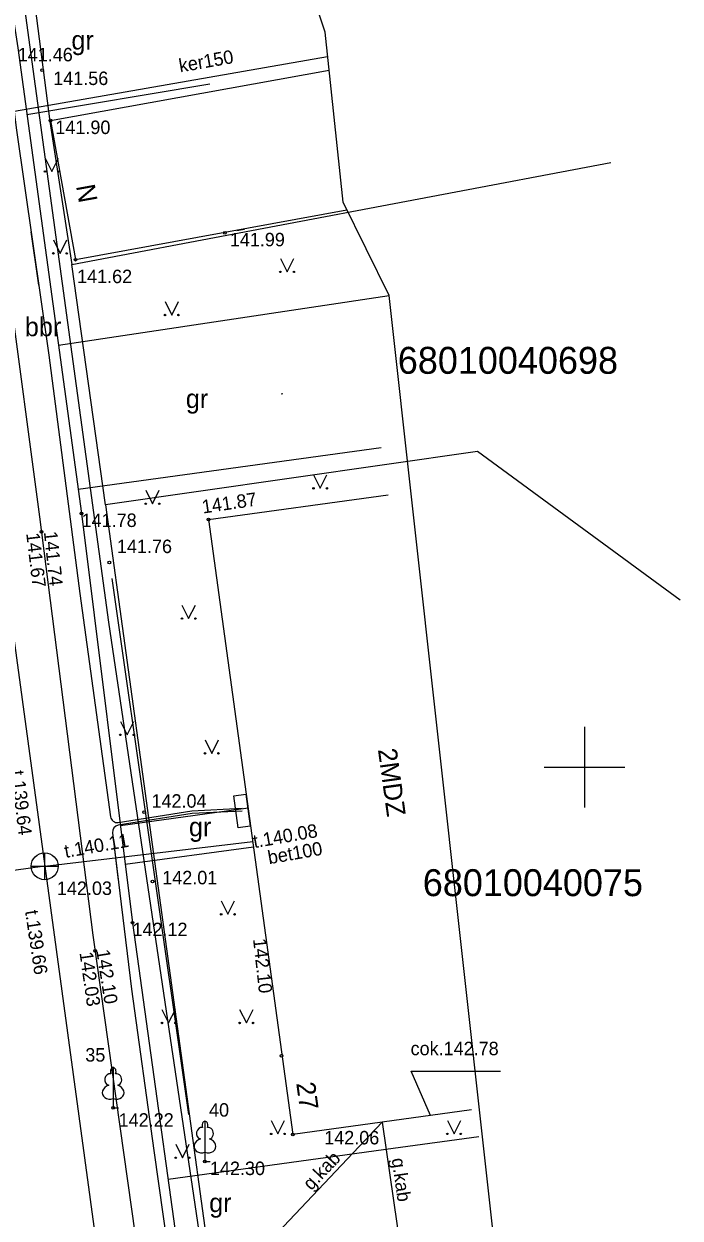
# Model space of a CAD drawing. Extents: x 728710 to 728960, y 272811 to 273475.
# Drawn here: x 728829.17 to 728853.55, y 273033.26 to 273077.6 of the extents above; entities that cross this region are included whole.
import ezdxf

# ---------------------------------------------------------------- set-up
doc = ezdxf.new("R2010")
doc.units = 0
for name, color, linetype in [('Level 10', 7, 'Continuous'), ('Level 15', 7, 'Continuous'), ('Level 20', 7, 'Continuous'), ('Level 23', 7, 'Continuous'), ('Level 29', 7, 'Continuous'), ('Level 3', 7, 'Continuous'), ('Level 36', 7, 'Continuous'), ('Level 4', 7, 'Continuous'), ('Level 48', 7, 'Continuous'), ('Level 5', 7, 'Continuous'), ('Level 50', 7, 'Continuous'), ('Level 56', 7, 'Continuous'), ('Level 57', 7, 'Continuous'), ('Level 58', 7, 'Continuous'), ('Level 59', 7, 'Continuous'), ('Level 60', 7, 'Continuous'), ('Level 62', 7, 'Continuous'), ('Level 9', 7, 'Continuous'), ('RAMI_UZMR_####_####_#', 7, 'Continuous'), ('RELJ_NOGA_####_####_#', 7, 'Continuous'), ('RELJ_NOGL_####_####_#', 7, 'Continuous'), ('ROBZ_ELEM_####_####_#', 7, 'Continuous'), ('ROBZ_KADS_####_TKST_#', 7, 'Continuous'), ('ROBZ_UZMR_####_####_#', 7, 'Continuous'), ('SAKT_VADV_PKAB_TKST_#', 7, 'Continuous'), ('TERT_ELEM_####_####_#', 7, 'Continuous'), ('TERT_KONT_####_####_#', 7, 'Continuous')]:
    doc.layers.add(name, color=color, linetype=linetype)

msp = doc.modelspace()

# ---------------------------------------------------------------- linework, layer by layer
at = {"layer": 'Level 10'}
for p, q in [((728850, 273051.5), (728850, 273050)), ((728848.5, 273050), (728850, 273050)), ((728850, 273050), (728850, 273048.5)), ((728850, 273050), (728851.5, 273050))]:
    msp.add_line(p, q, dxfattribs=at)
at = {"layer": 'Level 15'}
msp.add_lwpolyline([(728837.131, 273047.752), (728836.966, 273048.94), (728837.412, 273049.002), (728837.576, 273047.813)], close=True, dxfattribs=at)
at = {"layer": 'Level 20'}
msp.add_line((728838.728, 273063.858), (728838.788, 273063.88), dxfattribs=at)
at = {"layer": 'Level 23'}
for points in [[(728821.624, 273100.995), (728826.189, 273073.896), (728840.452, 273076.388)], [(728826.189, 273073.896), (728833.694, 273018.747), (728821.168, 273017.069)], [(728829.942, 273046.322), (728837.671, 273047.239)], [(728829.942, 273046.322), (728821.163, 273045.101)]]:
    msp.add_lwpolyline(points, dxfattribs=at)
at = {"layer": 'Level 29'}
for p, q in [((728829.942, 273045.822), (728829.942, 273046.822)), ((728829.442, 273046.322), (728830.442, 273046.322))]:
    msp.add_line(p, q, dxfattribs=at)
msp.add_circle((728829.942, 273046.322), 0.5, dxfattribs=at)
at = {"layer": 'Level 3'}
for p, q in [((728830.155, 273074.012), (728840.506, 273075.886)), ((728830.155, 273074.012), (728831.09, 273068.845)), ((728831.09, 273068.845), (728841.169, 273070.698)), ((728836.029, 273059.195), (728842.701, 273060.111)), ((728836.029, 273059.195), (728839.164, 273036.364)), ((728845.796, 273037.275), (728839.164, 273036.364))]:
    msp.add_line(p, q, dxfattribs=at)
at = {"layer": 'Level 36'}
for points in [[(728829.721, 273067.896), (728829.437, 273069.878)], [(728832.465, 273047.568), (728832.677, 273045.803)]]:
    msp.add_lwpolyline(points, dxfattribs=at)
at = {"layer": 'Level 4'}
for p, q in [((728832.754, 273047.833), (728837.5, 273048.485)), ((728832.933, 273046.393), (728837.697, 273047.047)), ((728842.887, 273035.853), (728846.065, 273036.289)), ((728834.526, 273034.705), (728842.887, 273035.853))]:
    msp.add_line(p, q, dxfattribs=at)
for points in [[(728845.654, 273100.85), (728832.719, 273098.413), (728826.071, 273097.316), (728825.017, 273097.001), (728824.765, 273096.832), (728824.532, 273096.455), (728824.532, 273096.455), (728826.161, 273084.877), (728827.437, 273076.575), (728829.749, 273059.3), (728831.728, 273043.761), (728834.021, 273027.538), (728834.782, 273021.709), (728836.279, 273011.943), (728839.357, 272993.501), (728839.499, 272992.383), (728841.21, 272978.381), (728843.301, 272966.86), (728843.797, 272965.94)], [(728845.919, 273099.374), (728832.98, 273096.936), (728826.409, 273095.852), (728826.143, 273095.772), (728827.647, 273085.083), (728828.941, 273076.709), (728831.314, 273059.418), (728833.202, 273044.226), (728835.526, 273027.512), (728836.266, 273021.924), (728837.76, 273012.18), (728840.331, 272994.327), (728840.331, 272994.327), (728840.331, 272994.327), (728842.687, 272979.229), (728844.615, 272968.066)], [(728829.28, 273074.24), (728836.077, 273075.379)], [(728830.456, 273065.669), (728842.745, 273067.512)], [(728831.189, 273060.327), (728842.448, 273061.866)]]:
    msp.add_lwpolyline(points, dxfattribs=at)
at = {"layer": 'Level 48'}
for centre in [(728829.851, 273075.885), (728830.153, 273074.009), (728836.634, 273069.841), (728831.09, 273068.845), (728831.314, 273059.418), (728836.029, 273059.195), (728829.82, 273058.739), (728832.344, 273057.603), (728833.634, 273048.333), (728833.949, 273045.759), (728833.202, 273044.226), (728831.819, 273043.183), (728838.738, 273039.285), (728832.488, 273037.348), (728839.164, 273036.361), (728835.896, 273035.354)]:
    msp.add_circle(centre, 0.05, dxfattribs=at)
at = {"layer": 'Level 5'}
msp.add_line((728837.08, 273069.929), (728837.37, 273069.982), dxfattribs=at)
at = {"layer": 'Level 9'}
msp.add_lwpolyline([(728844.281, 273037.067), (728843.563, 273038.713), (728846.876, 273038.713)], dxfattribs=at)
at = {"layer": 'RAMI_UZMR_####_####_#'}
for points in [[(728848.126, 273018.981), (728842.745, 273067.512), (728841.027, 273070.984), (728840.357, 273077.286), (728837.229, 273086.616), (728846.28, 273097.37), (728843.445, 273113.117), (728841.542, 273127.507), (728832.527, 273130.942), (728826.701, 273137.145), (728825.388, 273148.763), (728838.211, 273156.68), (728838.026, 273158.297), (728833.202, 273166.507)], [(728842.48, 273036.82), (728822.849, 273016.092)], [(728842.48, 273036.82), (728845.408, 273016.627)]]:
    msp.add_lwpolyline(points, dxfattribs=at)
at = {"layer": 'RELJ_NOGL_####_####_#'}
msp.add_lwpolyline([(728835.303, 273037.107), (728832.452, 273057.006)], dxfattribs=at)
at = {"layer": 'ROBZ_ELEM_####_####_#'}
msp.add_lwpolyline([(728827.017, 273094.024), (728832.315, 273055.38), (728845.254, 272968.134)], dxfattribs=at)
at = {"layer": 'ROBZ_UZMR_####_####_#'}
for p, q in [((728829.532, 273078.616), (728830.131, 273073.976)), ((728830.131, 273073.976), (728830.956, 273068.668)), ((728830.956, 273068.668), (728850.979, 273072.456)), ((728832.202, 273059.745), (728830.956, 273068.668)), ((728846.023, 273061.719), (728832.202, 273059.745)), ((728853.549, 273056.205), (728846.023, 273061.719)), ((728832.202, 273059.745), (728837.586, 273020.598))]:
    msp.add_line(p, q, dxfattribs=at)
at = {"layer": 'TERT_ELEM_####_####_#'}
for points in [[(728828.441, 273077.276), (728828.896, 273073.653), (728830.094, 273065.295), (728831.248, 273056.446), (728832.388, 273048.159)], [(728837.284, 273048.364), (728835.419, 273048.282), (728832.674, 273047.845)], [(728832.675, 273047.947), (728835.409, 273048.382), (728837.284, 273048.474)], [(728832.465, 273047.568), (728833.163, 273041.758), (728834, 273035.77), (728836.422, 273018.61), (728837.731, 273009.628), (728838.803, 273002.448), (728839.303, 272998.864)]]:
    msp.add_lwpolyline(points, dxfattribs=at)
for centre, start, end in [((728832.636, 273048.194), 187.8357, 279.0446), ((728832.713, 273047.598), 99.0446, 186.8531)]:
    msp.add_arc(centre, 0.25, start, end, dxfattribs=at)
at = {"layer": 'TERT_KONT_####_####_#'}
for p, q in [((728829.954, 273072.618), (728830.204, 273072.118)), ((728830.204, 273072.118), (728830.454, 273072.618)), ((728830.264, 273069.578), (728830.514, 273069.078)), ((728830.514, 273069.078), (728830.764, 273069.578)), ((728838.699, 273068.891), (728838.949, 273068.391)), ((728838.949, 273068.391), (728839.199, 273068.891)), ((728834.412, 273067.29), (728834.662, 273066.79)), ((728834.662, 273066.79), (728834.912, 273067.29)), ((728839.928, 273060.854), (728840.178, 273060.354)), ((728840.178, 273060.354), (728840.428, 273060.854)), ((728833.698, 273060.282), (728833.948, 273059.782)), ((728833.948, 273059.782), (728834.198, 273060.282)), ((728835.041, 273056.02), (728835.291, 273055.52)), ((728835.291, 273055.52), (728835.541, 273056.02)), ((728832.755, 273051.7), (728833.005, 273051.2)), ((728833.005, 273051.2), (728833.255, 273051.7)), ((728835.898, 273051.014), (728836.148, 273050.514)), ((728836.148, 273050.514), (728836.398, 273051.014)), ((728836.499, 273045.036), (728836.749, 273044.536)), ((728836.749, 273044.536), (728836.999, 273045.036)), ((728834.298, 273041.002), (728834.548, 273040.502)), ((728834.548, 273040.502), (728834.798, 273041.002)), ((728837.185, 273041.002), (728837.435, 273040.502)), ((728837.435, 273040.502), (728837.685, 273041.002)), ((728832.488, 273037.695), (728832.488, 273037.348)), ((728832.488, 273037.348), (728832.688, 273037.348)), ((728838.356, 273036.883), (728838.606, 273036.383)), ((728838.606, 273036.383), (728838.856, 273036.883)), ((728844.901, 273036.883), (728845.151, 273036.383)), ((728845.151, 273036.383), (728845.401, 273036.883)), ((728834.812, 273035.997), (728835.062, 273035.497)), ((728835.062, 273035.497), (728835.312, 273035.997)), ((728835.896, 273035.701), (728835.896, 273035.354)), ((728835.896, 273035.354), (728836.096, 273035.354))]:
    msp.add_line(p, q, dxfattribs=at)
for points in [[(728832.488, 273038.848), (728832.488, 273037.695)], [(728832.577, 273038.615), (728832.576, 273038.616)], [(728835.896, 273036.854), (728835.896, 273035.701)], [(728835.986, 273036.622), (728835.985, 273036.623)]]:
    msp.add_lwpolyline(points, dxfattribs=at)
for centre, radius in [((728829.953, 273072.118), 0.028), ((728830.453, 273072.118), 0.0263), ((728830.264, 273069.077), 0.028), ((728830.764, 273069.077), 0.0263), ((728838.699, 273068.391), 0.028), ((728839.199, 273068.391), 0.0263), ((728834.412, 273066.789), 0.028), ((728834.912, 273066.789), 0.0263), ((728839.928, 273060.353), 0.028), ((728840.428, 273060.353), 0.0263), ((728833.697, 273059.781), 0.028), ((728834.197, 273059.781), 0.0263), ((728835.041, 273055.519), 0.028), ((728835.541, 273055.519), 0.0263), ((728832.754, 273051.2), 0.028), ((728833.254, 273051.2), 0.0263), ((728835.898, 273050.513), 0.028), ((728836.398, 273050.513), 0.0263), ((728836.498, 273044.535), 0.028), ((728836.998, 273044.535), 0.0263), ((728834.298, 273040.502), 0.028), ((728834.798, 273040.502), 0.0263), ((728837.184, 273040.502), 0.028), ((728837.684, 273040.502), 0.0263), ((728838.356, 273036.383), 0.028), ((728838.856, 273036.383), 0.0263), ((728844.901, 273036.383), 0.028), ((728845.401, 273036.383), 0.0263), ((728834.812, 273035.496), 0.028), ((728835.312, 273035.496), 0.0263)]:
    msp.add_circle(centre, radius, dxfattribs=at)
for centre, major_axis, ratio, start_param, end_param in [((728832.488, 273038.698), (0, -0.15), 0.707107, 3.14537, 5.287485), ((728832.487, 273038.698), (0, -0.15), 0.707107, 0.995701, 3.137816), ((728832.359, 273038.403), (-0.039, -0.212), 0.861323, 3.141593, 6.283185), ((728832.616, 273038.403), (0.039, -0.212), 0.861323, 0, 3.141593), ((728832.398, 273037.941), (0.307, 0.095), 0.814445, 1.570796, 4.752015), ((728832.577, 273037.941), (-0.307, 0.095), 0.814445, 1.531171, 4.712389), ((728835.768, 273036.409), (-0.039, -0.212), 0.861323, 3.141593, 6.283185), ((728835.896, 273036.704), (0, -0.15), 0.707107, 3.14537, 5.287485), ((728835.896, 273036.704), (0, -0.15), 0.707107, 0.995701, 3.137816), ((728836.024, 273036.409), (0.039, -0.212), 0.861323, 0, 3.141593), ((728835.806, 273035.947), (0.307, 0.095), 0.814445, 1.570796, 4.752015), ((728835.986, 273035.947), (-0.307, 0.095), 0.814445, 1.531171, 4.712389)]:
    msp.add_ellipse(centre, major_axis=major_axis, ratio=ratio, start_param=start_param, end_param=end_param, dxfattribs=at)

# ---------------------------------------------------------------- texts
at = {"layer": 'Level 50'}
msp.add_text('cok.142.78', height=0.5, dxfattribs=at).set_placement((728843.537, 273039.305))
at = {"layer": 'Level 56'}
msp.add_text(' 142.03', height=0.5, dxfattribs=at).set_placement((728830.211, 273045.255))
at = {"layer": 'Level 57'}
for s, p in [('141.46', (728828.941, 273076.209)), (' 141.56', (728830.073, 273075.329)), (' 141.90', (728830.153, 273073.509)), (' 141.99', (728836.634, 273069.341)), (' 141.62', (728830.959, 273067.973)), ('141.78', (728831.314, 273058.918)), (' 141.76', (728832.441, 273057.95)), (' 142.04', (728833.724, 273048.495)), (' 142.01', (728834.124, 273045.65)), ('142.12', (728833.202, 273043.726)), (' 142.22', (728832.505, 273036.651)), (' 142.06', (728840.141, 273035.993)), (' 142.30', (728835.896, 273034.854))]:
    msp.add_text(s, height=0.5, dxfattribs=at).set_placement(p)
for s, rotation, p in [(' 141.87', 8.3972, (728835.638, 273059.389)), ('141.74', 275.9819, (728829.91, 273058.736)), ('141.67', 276.8258, (728829.253, 273058.68)), ('142.10', 278.9235, (728831.855, 273043.195)), (' 142.10', 276.3912, (728837.66, 273043.798)), ('142.03', 278.1002, (728831.233, 273043.113))]:
    msp.add_text(s, height=0.5, rotation=rotation, dxfattribs=at).set_placement(p)
at = {"layer": 'Level 58'}
for s, p in [('gr', (728830.935, 273076.644)), ('bbr', (728829.205, 273066.003)), ('gr', (728835.186, 273063.334)), ('gr', (728835.302, 273047.433)), ('gr', (728836.053, 273033.477))]:
    msp.add_text(s, height=0.7, dxfattribs=at).set_placement(p)
at = {"layer": 'Level 59'}
for s, rotation, p in [('N', 280.261, (728831.104, 273071.578)), ('2MDZ', 277.818, (728842.32, 273050.655))]:
    msp.add_text(s, height=0.7, rotation=rotation, dxfattribs=at).set_placement(p)
at = {"layer": 'Level 60'}
for s, rotation, p in [('ker150', 9.909, (728834.973, 273075.796)), ('t.139.64', 277.044, (728828.683, 273049.845)), ('t.140.08', 10.055, (728837.732, 273046.991)), ('t.140.11', 10.055, (728830.719, 273046.628)), ('bet100', 10.055, (728838.277, 273046.394)), ('t.139.66', 278.445, (728829.211, 273044.655))]:
    msp.add_text(s, height=0.5, rotation=rotation, dxfattribs=at).set_placement(p)
at = {"layer": 'Level 62'}
msp.add_text('27', height=0.7, rotation=277.818, dxfattribs=at).set_placement((728839.286, 273038.264))
at = {"layer": 'RELJ_NOGA_####_####_#'}
for s, p in [('35', (728831.451, 273039.068)), ('40', (728836.049, 273037.024))]:
    msp.add_text(s, height=0.5, dxfattribs=at).set_placement(p)
at = {"layer": 'ROBZ_KADS_####_TKST_#'}
for s, p in [('68010040698', (728843.061, 273064.607)), ('68010040075', (728843.989, 273045.211))]:
    msp.add_text(s, height=1, dxfattribs=at).set_placement(p)
at = {"layer": 'SAKT_VADV_PKAB_TKST_#'}
for rotation, p in [(46.5552, (728839.846, 273034.257)), (278.2496, (728842.829, 273035.455))]:
    msp.add_text('g.kab', height=0.5, rotation=rotation, dxfattribs=at).set_placement(p)

doc.saveas('drawing.dxf')
